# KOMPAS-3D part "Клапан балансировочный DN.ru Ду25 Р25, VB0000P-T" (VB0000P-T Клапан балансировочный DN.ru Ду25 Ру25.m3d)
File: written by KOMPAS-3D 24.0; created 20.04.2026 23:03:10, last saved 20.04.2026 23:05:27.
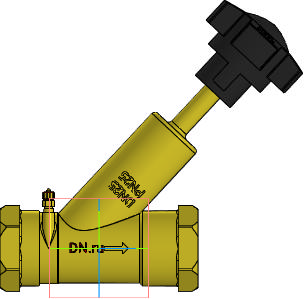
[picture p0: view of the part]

Document properties: Автор: DN.ru; Полное имя файла: E:\Работа\Зайцев\АУТСОРС\Диман\Балансировка\VB0000P-T Клапан балансировочный DN.ru Ду15-50 Ру25\DN25\VB0000P-T Клапан балансировочный DN.ru Ду25 Ру25.m3d

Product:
- Part/product: Клапан балансировочный DN.ru Ду25 Р25  | designation VB0000P-T
    Масса: 0.84
    Раздел спецификации: Прочие изделия
    Примечание: D080-01177

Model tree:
1. Операция без истории:1

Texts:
  VB0000P-T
